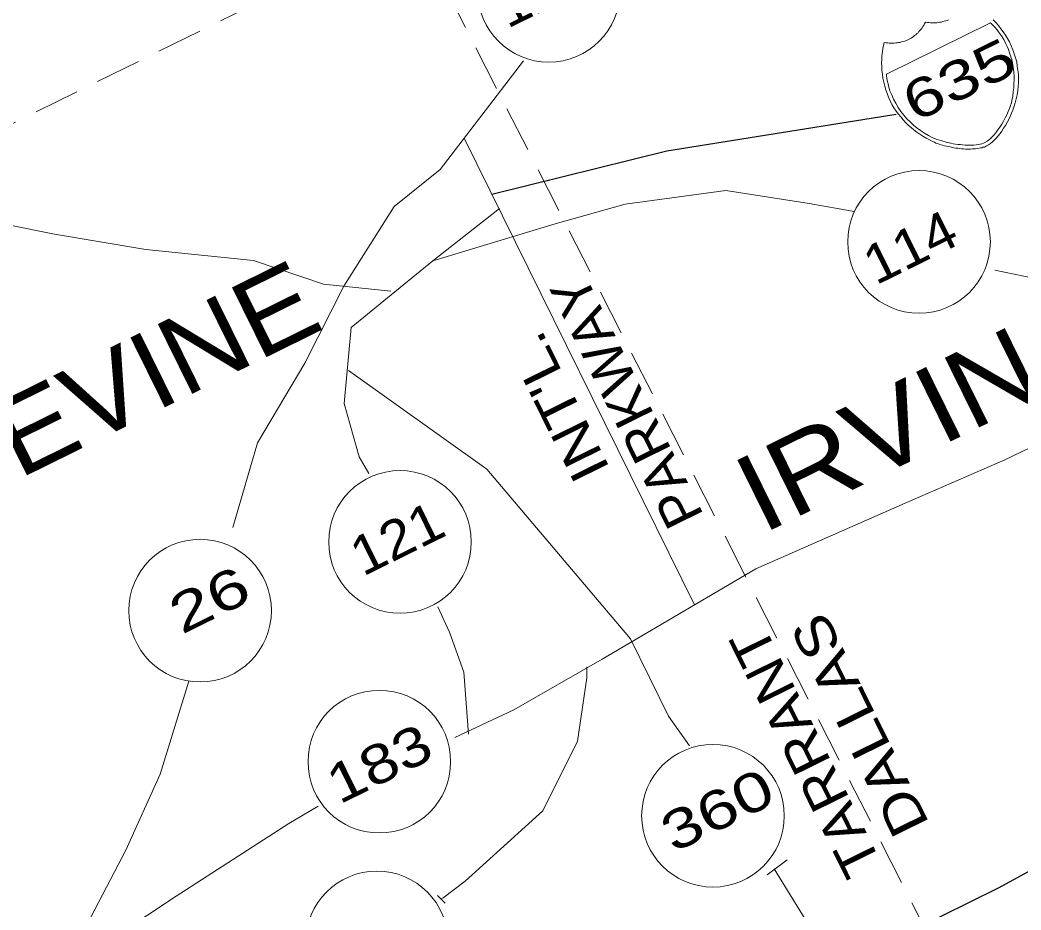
# Model space of a CAD drawing. Extents: x 2356606 to 2371222, y 6973096 to 6982644.
# Drawn here: x 2370920.3 to 2371051.8, y 6980470.1 to 6980586.9 of the extents above; entities that cross this region are included whole.
import ezdxf

# ---------------------------------------------------------------- set-up
doc = ezdxf.new("R2010")
doc.units = 0
doc.header["$LTSCALE"] = 2
doc.linetypes.add('MEDIUM_DASHED', pattern=[4.5, 3, -1.5])
doc.layers.add('62', color=7, linetype='Continuous', lineweight=13)
doc.layers.add('63', color=7, linetype='Continuous', lineweight=13)

msp = doc.modelspace()

# ---------------------------------------------------------------- linework, layer by layer
at = {"layer": '62', "linetype": 'MEDIUM_DASHED'}
for p, q in [((2371056.951, 6980641.227), (2370654.977, 6980442.841)), ((2370972, 6980599.301), (2371099.701, 6980348.989))]:
    msp.add_line(p, q, dxfattribs=at)
at = {"layer": '62'}
for p, q in [((2371008.873, 6980510.15), (2370978.638, 6980571.412)), ((2371023.96, 6980562.814), (2371029.871, 6980561.767)), ((2370974.548, 6980555.292), (2370983.311, 6980562.151)), ((2371070.142, 6980549.575), (2371048.328, 6980554.064)), ((2370960.194, 6980552.246), (2370969.022, 6980551.336)), ((2370951.513, 6980531.401), (2370948.262, 6980520.286)), ((2370964.886, 6980529.57), (2370966.124, 6980527.369)), ((2370976.741, 6980506.565), (2370975.189, 6980509.865)), ((2371000.467, 6980505.676), (2371005.488, 6980495.507)), ((2370994.744, 6980500.542), (2370994.773, 6980502.011)), ((2370938.756, 6980487.894), (2370942.484, 6980500.121)), ((2370985.163, 6980496.367), (2370977.446, 6980492.733)), ((2371005.488, 6980495.507), (2371008.223, 6980491.638)), ((2370955.63, 6980481.415), (2370959.494, 6980483.699)), ((2371018.451, 6980474.678), (2371021.038, 6980476.657)), ((2371025.887, 6980464.899), (2371019.329, 6980475.488)), ((2370978.786, 6980473.849), (2370975.886, 6980471.689)), ((2370975.143, 6980471.976), (2370976.144, 6980470.964)), ((2370975.603, 6980471.498), (2370975.886, 6980471.689))]:
    msp.add_line(p, q, dxfattribs=at)
for points in [[(2371047.247, 6980570.392), (2371047.083, 6980570.312), (2371046.941, 6980570.242), (2371046.761, 6980570.201), (2371046.61, 6980570.153), (2371046.429, 6980570.115), (2371046.248, 6980570.075), (2371046.015, 6980570.036), (2371045.802, 6980570.006), (2371045.604, 6980570.009), (2371045.382, 6980570), (2371045.14, 6980569.979), (2371044.921, 6980569.971), (2371044.666, 6980569.972), (2371044.465, 6980569.973), (2371044.204, 6980569.995), (2371043.951, 6980569.996), (2371043.713, 6980570.027), (2371043.441, 6980570.068), (2371043.199, 6980570.101), (2371042.956, 6980570.132), (2371042.708, 6980570.183), (2371042.445, 6980570.256), (2371042.205, 6980570.286), (2371041.971, 6980570.348), (2371041.721, 6980570.399), (2371041.491, 6980570.463), (2371041.248, 6980570.543), (2371041.027, 6980570.635), (2371040.776, 6980570.686), (2371040.565, 6980570.756), (2371040.385, 6980570.868), (2371040.135, 6980570.972), (2371039.733, 6980571.174), (2371039.29, 6980571.41), (2371038.879, 6980571.684), (2371038.487, 6980571.917), (2371038.094, 6980572.202), (2371037.684, 6980572.477), (2371037.333, 6980572.781), (2371036.963, 6980573.125), (2371036.601, 6980573.448), (2371036.271, 6980573.809), (2371035.963, 6980574.184), (2371035.651, 6980574.558), (2371035.354, 6980574.962), (2371035.073, 6980575.377), (2371034.793, 6980575.841), (2371034.564, 6980576.305), (2371034.354, 6980576.779), (2371034.176, 6980577.244), (2371034.009, 6980577.737), (2371033.86, 6980578.242), (2371033.731, 6980578.756), (2371033.623, 6980579.279), (2371033.576, 6980579.781), (2371033.488, 6980580.316), (2371033.473, 6980580.811), (2371033.453, 6980581.303), (2371033.467, 6980581.786), (2371033.489, 6980582.247), (2371033.552, 6980582.731), (2371033.595, 6980583.153), (2371033.688, 6980583.574), (2371033.781, 6980583.947), (2371034, 6980583.905), (2371034.254, 6980583.905), (2371034.464, 6980583.883), (2371034.664, 6980583.884), (2371034.896, 6980583.871), (2371035.099, 6980583.871), (2371035.31, 6980583.9), (2371035.511, 6980583.899), (2371035.683, 6980583.957), (2371035.904, 6980583.965), (2371036.074, 6980584.027), (2371036.276, 6980584.075), (2371036.476, 6980584.125), (2371036.629, 6980584.174), (2371036.79, 6980584.254), (2371036.992, 6980584.354), (2371037.154, 6980584.434), (2371037.316, 6980584.513), (2371037.486, 6980584.624), (2371037.63, 6980584.744), (2371037.771, 6980584.864), (2371037.941, 6980584.971), (2371038.083, 6980585.141), (2371038.234, 6980585.242), (2371038.355, 6980585.403), (2371038.489, 6980585.542), (2371038.65, 6980585.722), (2371038.761, 6980585.904), (2371038.883, 6980586.064), (2371038.996, 6980586.245), (2371039.107, 6980586.427), (2371039.227, 6980586.636), (2371039.448, 6980586.595), (2371039.659, 6980586.574), (2371039.891, 6980586.562), (2371040.095, 6980586.563)], [(2371040.095, 6980586.563), (2371040.305, 6980586.541), (2371040.526, 6980586.55), (2371040.697, 6980586.559), (2371040.94, 6980586.577), (2371041.111, 6980586.638), (2371041.312, 6980586.637), (2371041.483, 6980586.697), (2371041.685, 6980586.745), (2371041.866, 6980586.785), (2371042.059, 6980586.855), (2371042.22, 6980586.934)], [(2371048.087, 6980586.942), (2371048.435, 6980586.589), (2371048.787, 6980586.184), (2371049.116, 6980585.769), (2371049.427, 6980585.347), (2371049.735, 6980584.922), (2371049.974, 6980584.486), (2371050.245, 6980584.043), (2371050.452, 6980583.518), (2371050.693, 6980582.986), (2371050.849, 6980582.461), (2371051.049, 6980581.958), (2371051.187, 6980581.424), (2371051.263, 6980580.859), (2371051.343, 6980580.344), (2371051.41, 6980579.802), (2371051.427, 6980579.257), (2371051.413, 6980578.724), (2371051.401, 6980578.189), (2371051.338, 6980577.656), (2371051.246, 6980577.085), (2371051.13, 6980576.55), (2371050.989, 6980576.028), (2371050.814, 6980575.465), (2371050.683, 6980575.074), (2371050.529, 6980574.672), (2371050.336, 6980574.251), (2371050.152, 6980573.859), (2371049.938, 6980573.475), (2371049.716, 6980573.067), (2371049.471, 6980572.695), (2371049.248, 6980572.334), (2371049.025, 6980572.025), (2371048.761, 6980571.692), (2371048.511, 6980571.391), (2371048.235, 6980571.132), (2371047.994, 6980570.91), (2371047.75, 6980570.691), (2371047.487, 6980570.511), (2371047.247, 6980570.392)], [(2370962.848, 6980551.951), (2370969.464, 6980562.443), (2370975.495, 6980567.301), (2370986.42, 6980581.575)], [(2370985.163, 6980496.367), (2370996.759, 6980503.018), (2371016.927, 6980514.876), (2371036.537, 6980523.502), (2371049.626, 6980529.16), (2371065.881, 6980536.955), (2371074.048, 6980543.748), (2371081.532, 6980555.422), (2371090.442, 6980567.322), (2371093.524, 6980570.125)], [(2370990.595, 6980560.151), (2370999.767, 6980562.72), (2371012.989, 6980564.553), (2371023.96, 6980562.814)], [(2370694.565, 6980506.465), (2370701.888, 6980515.578), (2370713.884, 6980523.555), (2370731.58, 6980524.057), (2370741.804, 6980528.05), (2370757.11, 6980527.799), (2370767.604, 6980527.734), (2370776.186, 6980528.608), (2370787.329, 6980531.698), (2370795.99, 6980534.996), (2370807.086, 6980539.971), (2370819.598, 6980546.748), (2370836.86, 6980552.707), (2370847.791, 6980557.198), (2370860.544, 6980561.712), (2370876.753, 6980562.379), (2370892.297, 6980562.702), (2370906.789, 6980562.427), (2370924.884, 6980558.812), (2370936.86, 6980556.765), (2370950.983, 6980555.354), (2370960.194, 6980552.246)], [(2370963.818, 6980546.533), (2370974.548, 6980555.292), (2370990.595, 6980560.151)], [(2370962.848, 6980551.951), (2370957.714, 6980541.865), (2370951.513, 6980531.401)], [(2370964.886, 6980529.57), (2370962.909, 6980536.576), (2370963.818, 6980546.533)], [(2371000.467, 6980505.676), (2370981.623, 6980527.942), (2370963.465, 6980540.89)], [(2370979.219, 6980493.157), (2370978.588, 6980501.301), (2370976.741, 6980506.565)], [(2370978.786, 6980473.849), (2370988.979, 6980483.093), (2370993.526, 6980492.238), (2370994.744, 6980500.542)], [(2370938.756, 6980487.894), (2370934.235, 6980477.93), (2370925.608, 6980461.455)], [(2370925.246, 6980461.577), (2370940.846, 6980471.91), (2370955.63, 6980481.415)]]:
    msp.add_lwpolyline(points, dxfattribs=at)
msp.add_lwpolyline([(2371047.751, 6980586.551), (2371034.09, 6980579.809), (2371034.109, 6980579.567), (2371034.148, 6980579.285), (2371034.206, 6980578.964), (2371034.314, 6980578.542), (2371034.412, 6980578.086), (2371034.55, 6980577.603), (2371034.779, 6980577.089), (2371035.03, 6980576.535), (2371035.327, 6980575.978), (2371035.626, 6980575.423), (2371035.985, 6980574.898), (2371036.376, 6980574.415), (2371036.776, 6980573.96), (2371037.186, 6980573.536), (2371037.648, 6980573.11), (2371038.11, 6980572.736), (2371038.581, 6980572.392), (2371039.084, 6980572.037), (2371039.624, 6980571.75), (2371040.166, 6980571.465), (2371040.759, 6980571.231), (2371041.352, 6980571.046), (2371041.943, 6980570.861), (2371042.557, 6980570.738), (2371042.859, 6980570.636), (2371043.171, 6980570.615), (2371043.471, 6980570.562), (2371043.805, 6980570.551), (2371044.096, 6980570.517), (2371044.417, 6980570.476), (2371044.719, 6980570.475), (2371045.021, 6980570.472), (2371045.313, 6980570.492), (2371045.584, 6980570.501), (2371045.877, 6980570.519), (2371046.129, 6980570.569), (2371046.382, 6980570.616), (2371046.602, 6980570.677), (2371046.823, 6980570.735), (2371047.025, 6980570.835), (2371047.299, 6980570.995), (2371047.614, 6980571.224), (2371047.887, 6980571.486), (2371048.179, 6980571.806), (2371048.462, 6980572.096), (2371048.726, 6980572.478), (2371048.969, 6980572.849), (2371049.235, 6980573.228), (2371049.477, 6980573.649), (2371049.69, 6980574.082), (2371049.894, 6980574.482), (2371050.065, 6980574.895), (2371050.251, 6980575.286), (2371050.382, 6980575.679), (2371050.506, 6980576.039), (2371050.547, 6980576.363), (2371050.672, 6980576.926), (2371050.723, 6980577.48), (2371050.797, 6980577.993), (2371050.83, 6980578.537), (2371050.851, 6980579.05), (2371050.845, 6980579.522), (2371050.817, 6980579.986), (2371050.759, 6980580.46), (2371050.699, 6980580.93), (2371050.643, 6980581.356), (2371050.524, 6980581.799), (2371050.397, 6980582.211), (2371050.266, 6980582.625), (2371050.118, 6980583.029), (2371049.949, 6980583.422), (2371049.76, 6980583.805), (2371049.493, 6980584.349), (2371049.203, 6980584.834), (2371048.901, 6980585.237), (2371048.643, 6980585.611), (2371048.351, 6980585.946), (2371048.112, 6980586.177), (2371047.914, 6980586.38)], close=True, dxfattribs=at)
at = {"layer": '62', "lineweight": 25}
for points in [[(2371035.349, 6980574.51), (2371005.267, 6980569.675), (2370982.303, 6980563.987)], [(2371119.806, 6980516.871), (2371108.589, 6980509.904), (2371091.896, 6980498.532), (2371071.569, 6980485.363), (2371048.771, 6980472.932), (2371022.721, 6980460.075), (2370994.479, 6980445.157), (2370978.671, 6980436.103)]]:
    msp.add_lwpolyline(points, dxfattribs=at)
at = {"layer": '62'}
for centre in [(2370989.769, 6980590.747), (2371038.365, 6980557.782), (2370970.228, 6980518.397), (2370943.983, 6980509.377), (2370967.514, 6980489.549), (2371011.314, 6980482.452), (2370967.199, 6980465.817)]:
    msp.add_circle(centre, 9.364, dxfattribs=at)
at = {"layer": '63', "linetype": 'MEDIUM_DASHED'}
for p, q in [((2371056.951, 6980641.227), (2370654.977, 6980442.841)), ((2370972, 6980599.301), (2371099.701, 6980348.989))]:
    msp.add_line(p, q, dxfattribs=at)
at = {"layer": '63'}
for p, q in [((2371008.873, 6980510.15), (2370978.638, 6980571.412)), ((2371023.96, 6980562.814), (2371029.871, 6980561.767)), ((2370974.548, 6980555.292), (2370983.311, 6980562.151)), ((2371070.142, 6980549.575), (2371048.328, 6980554.064)), ((2370960.194, 6980552.246), (2370969.022, 6980551.336)), ((2370951.513, 6980531.401), (2370948.262, 6980520.286)), ((2370964.886, 6980529.57), (2370966.124, 6980527.369)), ((2370976.741, 6980506.565), (2370975.189, 6980509.865)), ((2371000.467, 6980505.676), (2371005.488, 6980495.507)), ((2370994.744, 6980500.542), (2370994.773, 6980502.011)), ((2370938.756, 6980487.894), (2370942.484, 6980500.121)), ((2370985.163, 6980496.367), (2370977.446, 6980492.733)), ((2371005.488, 6980495.507), (2371008.223, 6980491.638)), ((2370955.63, 6980481.415), (2370959.494, 6980483.699)), ((2371018.451, 6980474.678), (2371021.038, 6980476.657)), ((2371025.887, 6980464.899), (2371019.329, 6980475.488)), ((2370978.786, 6980473.849), (2370975.886, 6980471.689)), ((2370975.143, 6980471.976), (2370976.144, 6980470.964)), ((2370975.603, 6980471.498), (2370975.886, 6980471.689))]:
    msp.add_line(p, q, dxfattribs=at)
for points in [[(2371047.247, 6980570.392), (2371047.083, 6980570.312), (2371046.941, 6980570.242), (2371046.761, 6980570.201), (2371046.61, 6980570.153), (2371046.429, 6980570.115), (2371046.248, 6980570.075), (2371046.015, 6980570.036), (2371045.802, 6980570.006), (2371045.604, 6980570.009), (2371045.382, 6980570), (2371045.14, 6980569.979), (2371044.921, 6980569.971), (2371044.666, 6980569.972), (2371044.465, 6980569.973), (2371044.204, 6980569.995), (2371043.951, 6980569.996), (2371043.713, 6980570.027), (2371043.441, 6980570.068), (2371043.199, 6980570.101), (2371042.956, 6980570.132), (2371042.708, 6980570.183), (2371042.445, 6980570.256), (2371042.205, 6980570.286), (2371041.971, 6980570.348), (2371041.721, 6980570.399), (2371041.491, 6980570.463), (2371041.248, 6980570.543), (2371041.027, 6980570.635), (2371040.776, 6980570.686), (2371040.565, 6980570.756), (2371040.385, 6980570.868), (2371040.135, 6980570.972), (2371039.733, 6980571.174), (2371039.29, 6980571.41), (2371038.879, 6980571.684), (2371038.487, 6980571.917), (2371038.094, 6980572.202), (2371037.684, 6980572.477), (2371037.333, 6980572.781), (2371036.963, 6980573.125), (2371036.601, 6980573.448), (2371036.271, 6980573.809), (2371035.963, 6980574.184), (2371035.651, 6980574.558), (2371035.354, 6980574.962), (2371035.073, 6980575.377), (2371034.793, 6980575.841), (2371034.564, 6980576.305), (2371034.354, 6980576.779), (2371034.176, 6980577.244), (2371034.009, 6980577.737), (2371033.86, 6980578.242), (2371033.731, 6980578.756), (2371033.623, 6980579.279), (2371033.576, 6980579.781), (2371033.488, 6980580.316), (2371033.473, 6980580.811), (2371033.453, 6980581.303), (2371033.467, 6980581.786), (2371033.489, 6980582.247), (2371033.552, 6980582.731), (2371033.595, 6980583.153), (2371033.688, 6980583.574), (2371033.781, 6980583.947), (2371034, 6980583.905), (2371034.254, 6980583.905), (2371034.464, 6980583.883), (2371034.664, 6980583.884), (2371034.896, 6980583.871), (2371035.099, 6980583.871), (2371035.31, 6980583.9), (2371035.511, 6980583.899), (2371035.683, 6980583.957), (2371035.904, 6980583.965), (2371036.074, 6980584.027), (2371036.276, 6980584.075), (2371036.476, 6980584.125), (2371036.629, 6980584.174), (2371036.79, 6980584.254), (2371036.992, 6980584.354), (2371037.154, 6980584.434), (2371037.316, 6980584.513), (2371037.486, 6980584.624), (2371037.63, 6980584.744), (2371037.771, 6980584.864), (2371037.941, 6980584.971), (2371038.083, 6980585.141), (2371038.234, 6980585.242), (2371038.355, 6980585.403), (2371038.489, 6980585.542), (2371038.65, 6980585.722), (2371038.761, 6980585.904), (2371038.883, 6980586.064), (2371038.996, 6980586.245), (2371039.107, 6980586.427), (2371039.227, 6980586.636), (2371039.448, 6980586.595), (2371039.659, 6980586.574), (2371039.891, 6980586.562), (2371040.095, 6980586.563)], [(2371040.095, 6980586.563), (2371040.305, 6980586.541), (2371040.526, 6980586.55), (2371040.697, 6980586.559), (2371040.94, 6980586.577), (2371041.111, 6980586.638), (2371041.312, 6980586.637), (2371041.483, 6980586.697), (2371041.685, 6980586.745), (2371041.866, 6980586.785), (2371042.059, 6980586.855), (2371042.22, 6980586.934)], [(2371048.087, 6980586.942), (2371048.435, 6980586.589), (2371048.787, 6980586.184), (2371049.116, 6980585.769), (2371049.427, 6980585.347), (2371049.735, 6980584.922), (2371049.974, 6980584.486), (2371050.245, 6980584.043), (2371050.452, 6980583.518), (2371050.693, 6980582.986), (2371050.849, 6980582.461), (2371051.049, 6980581.958), (2371051.187, 6980581.424), (2371051.263, 6980580.859), (2371051.343, 6980580.344), (2371051.41, 6980579.802), (2371051.427, 6980579.257), (2371051.413, 6980578.724), (2371051.401, 6980578.189), (2371051.338, 6980577.656), (2371051.246, 6980577.085), (2371051.13, 6980576.55), (2371050.989, 6980576.028), (2371050.814, 6980575.465), (2371050.683, 6980575.074), (2371050.529, 6980574.672), (2371050.336, 6980574.251), (2371050.152, 6980573.859), (2371049.938, 6980573.475), (2371049.716, 6980573.067), (2371049.471, 6980572.695), (2371049.248, 6980572.334), (2371049.025, 6980572.025), (2371048.761, 6980571.692), (2371048.511, 6980571.391), (2371048.235, 6980571.132), (2371047.994, 6980570.91), (2371047.75, 6980570.691), (2371047.487, 6980570.511), (2371047.247, 6980570.392)], [(2370962.848, 6980551.951), (2370969.464, 6980562.443), (2370975.495, 6980567.301), (2370986.42, 6980581.575)], [(2370985.163, 6980496.367), (2370996.759, 6980503.018), (2371016.927, 6980514.876), (2371036.537, 6980523.502), (2371049.626, 6980529.16), (2371065.881, 6980536.955), (2371074.048, 6980543.748), (2371081.532, 6980555.422), (2371090.442, 6980567.322), (2371093.524, 6980570.125)], [(2370990.595, 6980560.151), (2370999.767, 6980562.72), (2371012.989, 6980564.553), (2371023.96, 6980562.814)], [(2370694.565, 6980506.465), (2370701.888, 6980515.578), (2370713.884, 6980523.555), (2370731.58, 6980524.057), (2370741.804, 6980528.05), (2370757.11, 6980527.799), (2370767.604, 6980527.734), (2370776.186, 6980528.608), (2370787.329, 6980531.698), (2370795.99, 6980534.996), (2370807.086, 6980539.971), (2370819.598, 6980546.748), (2370836.86, 6980552.707), (2370847.791, 6980557.198), (2370860.544, 6980561.712), (2370876.753, 6980562.379), (2370892.297, 6980562.702), (2370906.789, 6980562.427), (2370924.884, 6980558.812), (2370936.86, 6980556.765), (2370950.983, 6980555.354), (2370960.194, 6980552.246)], [(2370963.818, 6980546.533), (2370974.548, 6980555.292), (2370990.595, 6980560.151)], [(2370962.848, 6980551.951), (2370957.714, 6980541.865), (2370951.513, 6980531.401)], [(2370964.886, 6980529.57), (2370962.909, 6980536.576), (2370963.818, 6980546.533)], [(2371000.467, 6980505.676), (2370981.623, 6980527.942), (2370963.465, 6980540.89)], [(2370979.219, 6980493.157), (2370978.588, 6980501.301), (2370976.741, 6980506.565)], [(2370978.786, 6980473.849), (2370988.979, 6980483.093), (2370993.526, 6980492.238), (2370994.744, 6980500.542)], [(2370938.756, 6980487.894), (2370934.235, 6980477.93), (2370925.608, 6980461.455)], [(2370925.246, 6980461.577), (2370940.846, 6980471.91), (2370955.63, 6980481.415)]]:
    msp.add_lwpolyline(points, dxfattribs=at)
msp.add_lwpolyline([(2371047.751, 6980586.551), (2371034.09, 6980579.809), (2371034.109, 6980579.567), (2371034.148, 6980579.285), (2371034.206, 6980578.964), (2371034.314, 6980578.542), (2371034.412, 6980578.086), (2371034.55, 6980577.603), (2371034.779, 6980577.089), (2371035.03, 6980576.535), (2371035.327, 6980575.978), (2371035.626, 6980575.423), (2371035.985, 6980574.898), (2371036.376, 6980574.415), (2371036.776, 6980573.96), (2371037.186, 6980573.536), (2371037.648, 6980573.11), (2371038.11, 6980572.736), (2371038.581, 6980572.392), (2371039.084, 6980572.037), (2371039.624, 6980571.75), (2371040.166, 6980571.465), (2371040.759, 6980571.231), (2371041.352, 6980571.046), (2371041.943, 6980570.861), (2371042.557, 6980570.738), (2371042.859, 6980570.636), (2371043.171, 6980570.615), (2371043.471, 6980570.562), (2371043.805, 6980570.551), (2371044.096, 6980570.517), (2371044.417, 6980570.476), (2371044.719, 6980570.475), (2371045.021, 6980570.472), (2371045.313, 6980570.492), (2371045.584, 6980570.501), (2371045.877, 6980570.519), (2371046.129, 6980570.569), (2371046.382, 6980570.616), (2371046.602, 6980570.677), (2371046.823, 6980570.735), (2371047.025, 6980570.835), (2371047.299, 6980570.995), (2371047.614, 6980571.224), (2371047.887, 6980571.486), (2371048.179, 6980571.806), (2371048.462, 6980572.096), (2371048.726, 6980572.478), (2371048.969, 6980572.849), (2371049.235, 6980573.228), (2371049.477, 6980573.649), (2371049.69, 6980574.082), (2371049.894, 6980574.482), (2371050.065, 6980574.895), (2371050.251, 6980575.286), (2371050.382, 6980575.679), (2371050.506, 6980576.039), (2371050.547, 6980576.363), (2371050.672, 6980576.926), (2371050.723, 6980577.48), (2371050.797, 6980577.993), (2371050.83, 6980578.537), (2371050.851, 6980579.05), (2371050.845, 6980579.522), (2371050.817, 6980579.986), (2371050.759, 6980580.46), (2371050.699, 6980580.93), (2371050.643, 6980581.356), (2371050.524, 6980581.799), (2371050.397, 6980582.211), (2371050.266, 6980582.625), (2371050.118, 6980583.029), (2371049.949, 6980583.422), (2371049.76, 6980583.805), (2371049.493, 6980584.349), (2371049.203, 6980584.834), (2371048.901, 6980585.237), (2371048.643, 6980585.611), (2371048.351, 6980585.946), (2371048.112, 6980586.177), (2371047.914, 6980586.38)], close=True, dxfattribs=at)
at = {"layer": '63', "lineweight": 25}
for points in [[(2371035.349, 6980574.51), (2371005.267, 6980569.675), (2370982.303, 6980563.987)], [(2371119.806, 6980516.871), (2371108.589, 6980509.904), (2371091.896, 6980498.532), (2371071.569, 6980485.363), (2371048.771, 6980472.932), (2371022.721, 6980460.075), (2370994.479, 6980445.157), (2370978.671, 6980436.103)]]:
    msp.add_lwpolyline(points, dxfattribs=at)
at = {"layer": '63'}
for centre in [(2370989.769, 6980590.747), (2371038.365, 6980557.782), (2370970.228, 6980518.397), (2370943.983, 6980509.377), (2370967.514, 6980489.549), (2371011.314, 6980482.452), (2370967.199, 6980465.817)]:
    msp.add_circle(centre, 9.364, dxfattribs=at)

# ---------------------------------------------------------------- texts
at = {"layer": '62'}
for s, height, rotation, width, p in [('121', 5.099, 26.268, 1.1, (2370984.316, 6980585.736)), ('635', 5.099, 26.268, 1.35, (2371037.85, 6980573.412)), ('114', 5.099, 26.268, 1.1, (2371032.71, 6980552.053)), ('GRAPEVINE', 10.21, 26.268, 1.1, (2370881.98, 6980507.75)), ('PARKWAY', 5.099, 116.268, 1.05, (2371010.171, 6980521.86)), ('IRVING', 10.21, 26.268, 1.15, (2371017.736, 6980519.343)), ("INT'L.", 5.099, 116.268, 1.15, (2370997.857, 6980527.952)), ('121', 5.099, 26.268, 1.1, (2370965.36, 6980513.82)), ('26', 5.099, 26.268, 1.4, (2370941.568, 6980506.194)), ('DALLAS', 5.099, 116.268, 1.2, (2371039.79, 6980481.372)), ('TARRANT', 5.099, 116.268, 1.1, (2371033.553, 6980476.061)), ('183', 5.099, 26.268, 1.25, (2370962.244, 6980483.877)), ('360', 5.099, 26.268, 1.35, (2371006.129, 6980477.53)), ('GRAND', 10.21, 26.268, 1.05, (2371049.119, 6980450.418))]:
    msp.add_text(s, height=height, rotation=rotation, dxfattribs=dict(at, width=width)).set_placement(p)
at = {"layer": '63'}
for s, height, rotation, width, p in [('121', 5.099, 26.268, 1.1, (2370984.316, 6980585.736)), ('635', 5.099, 26.268, 1.35, (2371037.85, 6980573.412)), ('114', 5.099, 26.268, 1.1, (2371032.71, 6980552.053)), ('GRAPEVINE', 10.21, 26.268, 1.1, (2370881.98, 6980507.75)), ('PARKWAY', 5.099, 116.268, 1.05, (2371010.171, 6980521.86)), ('IRVING', 10.21, 26.268, 1.15, (2371017.736, 6980519.343)), ("INT'L.", 5.099, 116.268, 1.15, (2370997.857, 6980527.952)), ('121', 5.099, 26.268, 1.1, (2370965.36, 6980513.82)), ('26', 5.099, 26.268, 1.4, (2370941.568, 6980506.194)), ('DALLAS', 5.099, 116.268, 1.2, (2371039.79, 6980481.372)), ('TARRANT', 5.099, 116.268, 1.1, (2371033.553, 6980476.061)), ('183', 5.099, 26.268, 1.25, (2370962.244, 6980483.877)), ('360', 5.099, 26.268, 1.35, (2371006.129, 6980477.53)), ('GRAND', 10.21, 26.268, 1.05, (2371049.119, 6980450.418))]:
    msp.add_text(s, height=height, rotation=rotation, dxfattribs=dict(at, width=width)).set_placement(p)

doc.saveas('drawing.dxf')
